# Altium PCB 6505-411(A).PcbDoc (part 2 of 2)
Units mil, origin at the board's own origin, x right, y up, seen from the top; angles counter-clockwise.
Board outline 1549.7 x 1971.6 mil, 4 copper layers (Top Layer, Mid-Layer 1, Mid-Layer 2, Bottom Layer); 80 components, 57 nets, 309 pads, 377 vias.
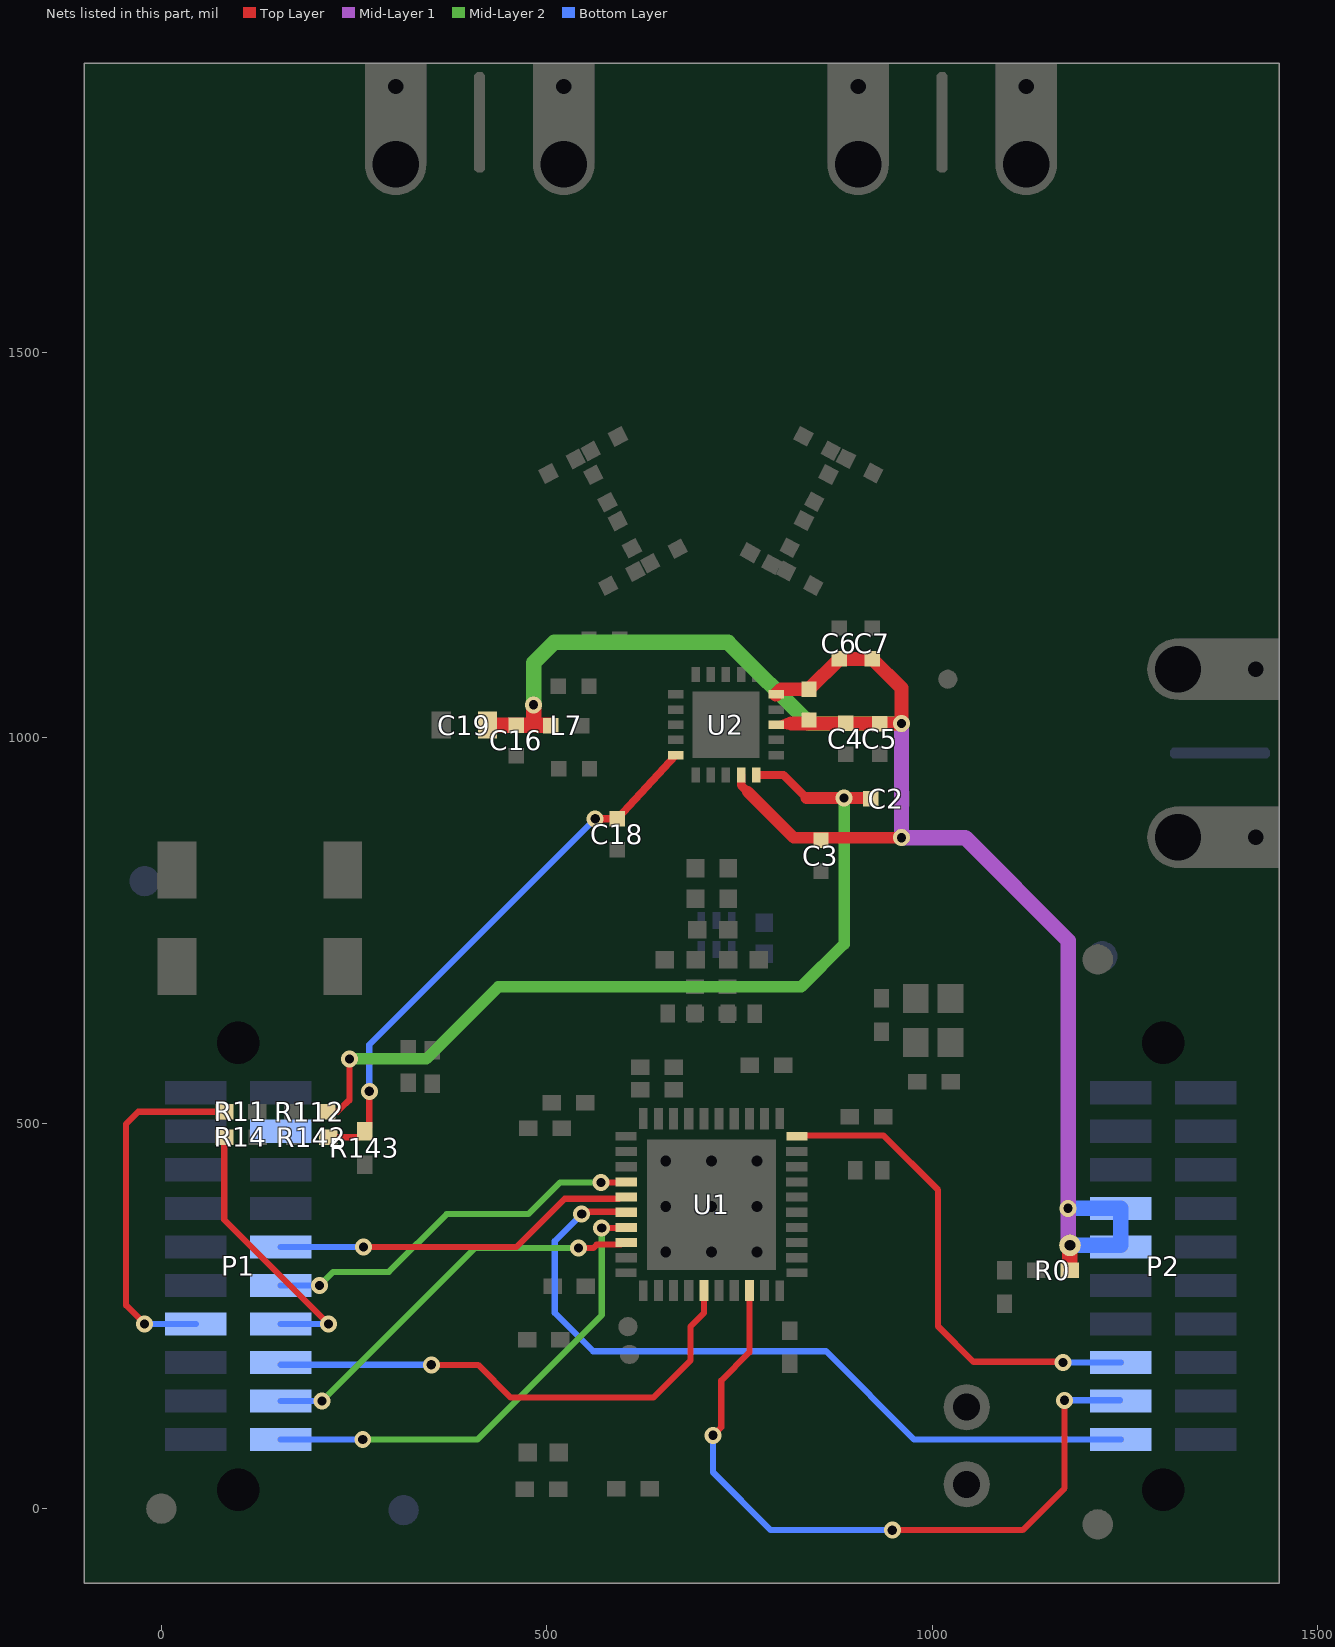
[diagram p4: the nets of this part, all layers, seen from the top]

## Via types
v1: diameter 22, hole 12, Top Layer to Bottom Layer, 281 vias
v2: diameter 22, hole 12, Top Layer to Bottom Layer, tented both sides, 96 vias

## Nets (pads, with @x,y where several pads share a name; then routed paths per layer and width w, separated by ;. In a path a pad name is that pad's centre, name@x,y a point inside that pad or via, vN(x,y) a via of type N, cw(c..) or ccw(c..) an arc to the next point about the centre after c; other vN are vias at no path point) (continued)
P1_1: P1.13 R11.1 | length 469.6
  Top Layer w8: v1(-21.7,239.6) -45.7,263.6 -45.7,499.1 -29.9,514.9 R11.1@81.4,514.9
  Bottom Layer w8: v1(-21.7,239.6) P1.13@44.8,239.6
P1_2: P2.17 U1.8 | length 946.4
  Top Layer w8: v1(715.8,95.1) 726.3,105.6 726.3,166.1 763,202.8 U1.8@763,275.2 ; v1(948.3,-27.9) 1117.3,-27.9 1171.8,26.6 v1(1171.8,140.6) v1@1168.8,140.6
  Bottom Layer w8: v1(715.8,95.1) 715.8,46.9 790.6,-27.9 v1(948.3,-27.9) ; v1(1171.8,140.6) P2.17@1243.8,140.6
P1_3: P1.4
P1_4: P1.14 R14.1 | length 360.3
  Top Layer w8: R14.1@81.6,481.9 81.6,374.8 v1(216.8,239.6)
  Bottom Layer w8: P1.14@154.8,239.6 v1(216.8,239.6)
P1_5: P1.16 U1.5 | length 659.4
  Top Layer w8: v1(350.3,186.6) 410.94,186.49 453.17,144.1 638.3,144.1 686.3,192.1 686.3,236.15 703.9,253.8 U1.5@703.9,275.2
  Bottom Layer w8: P1.16@154.8,186.6 v1(350.3,186.6)
P1_6: P1.18 U1.38 | length 525.5
  Top Layer w8: v1(541.3,338.1) 560.3,338.1 564.7,342.5 U1.38@596.3,342.5
  Mid-Layer 2 w8: v1(208.3,139.6) 406.8,338.1 v1(541.3,338.1)
  Bottom Layer w8: P1.18@154.8,139.6 v1(208.3,139.6)
P1_7: P1.20 U1.37 | length 626.2
  Top Layer w8: v1(571.3,364.2) U1.37@595.3,364.2
  Mid-Layer 2 w8: v1(261.3,89.6) 409.8,89.6 571.3,251.1 v1(571.3,364.2) v1@567.23,360.1
  Bottom Layer w8: P1.20@154.8,89.6 v1(261.3,89.6)
P2_0: P2.19 U1.36 | length 995.8
  Top Layer w8: v1@545.3,385.1 594,385.1 U1.36@595.3,383.8
  Bottom Layer w8: v1(545.3,382.1) 510.3,347.1 510.3,253.93 560.13,204.1 862.3,204.1 976.8,89.6 P2.19@1244.8,89.6
P2_1: P1.10 U1.35 | length 467
  Top Layer w8: v1(262.3,339.6) 460.78,339.6 523.28,402.1 593.9,402.1 U1.35@595.3,403.5
  Bottom Layer w8: P1.10@154.8,339.6 v1(262.3,339.6)
P2_2: P1.12 U1.34 | length 503.6
  Top Layer w8: v1(570.3,423.2) U1.34@603.1,423.2
  Mid-Layer 2 w8: v1(205.3,289.6) 222.8,307.1 295.3,307.1 370.3,382.1 476.3,382.1 517.4,423.2 v1(570.3,423.2)
  Bottom Layer w8: P1.12@154.8,289.6 v1(205.3,289.6)
RESET_N: P2.15 U1.20 | length 648.7
  Top Layer w8: U1.20@821.8,484.3 936.8,484.3 1007.58,413.52 1007.58,236.61 1053.5,190.6 1168.8,190.6 v1(1169.8,189.6)
  Bottom Layer w8: v1(1169.8,189.6) P2.15@1244.8,189.6
RX_EN: C18.2 R142.1 R143.1 U2.20 | length 720.4
  Top Layer w8: R142.1@216.7,481.9 256.5,481.9 259.04,484.42 261.19,486.55 264.08,489.42 269.8,495.1 v1(269.8,541.4)
  Top Layer w10: v1(562.89,894.88) 563.08,895.07 C18.2@591.4,895.07 U2.20@667.31,977.55
  Bottom Layer w8: v1(269.8,541.4) 269.8,601.79 v1(562.89,894.88)
TX_EN: C2.2 R112.1 U2.5 | length 1143.7
  Top Layer w8: R112.1@214.2,514.9 228.3,514.9 228.3,515.1 234,520.9 234.3,520.9 242.8,529.4 244,529.4 v1(244,583.4)
  Top Layer w10: U2.5@771.84,951.76 807.2,951.76 836.99,921.98
  Top Layer w15: 836.99,921.98 v1(885.7,921.98) C2.2@920.3,921.98
  Mid-Layer 2 w15: v1(244,583.4) 343.6,583.4 437.3,677.1 830.3,677.1 885.7,732.5 v1(885.7,921.98)
VDD: C3.2 C4.2 C5.2 C6.2 C7.2 C16.2 C19.2 L7.2 P2.7 P2.9 pad.1@840.2,1063.1 pad.1@1178.8,341.6 pad.2 R0.2 U2.4 U2.8 U2.10 | length 2486.5
  Top Layer w7: 814.38,1023.74 U2.8@797.63,1016.92 ; 817.44,1018.64 U2.8@797.63,1016.92 ; 817.52,1013.09 U2.8@797.63,1016.92
  Top Layer w11: 752.16,938.47 752.16,938.56 ; U2.4@752.16,951.76 752.16,938.56 ; 760.72,930 752.16,938.56 ; C3.2@860.44,871.77 C3.2@861.78,870.42
  Top Layer w15: 760.72,930 820.29,870.42 861.78,870.42 v1(960.3,870.42)
  Top Layer w18: U2.10@797.63,1056.29 804.44,1063.1 pad.1@840.2,1063.1 C6.2@879.6,1102.5 C7.2@922.3,1102.5 960.2,1064.6 v2(960.2,1018.64) 817.44,1018.64
  Top Layer w20: C19.2@423.2,1016.57 C16.2@460.4,1016.57 L7.2@504.71,1016.57 ; 482.89,1017.29 v2(482.89,1042.9) ; R0.2@1178.4,309.6 1178.4,339.6 1178.8,339.6 pad.1@1178.8,341.6
  Mid-Layer 1 w20: v1@960.2,871.02 v2(960.2,1018.64) ; v1(960.3,870.42) 1042.94,870.42 1176.3,737.06 v1(1176.3,389.6) pad.1@1176.3,341.6
  Mid-Layer 2 w11: pad.1@1178.8,339.6 pad.1@1178.8,341.6
  Mid-Layer 2 w20: v2(482.89,1042.9) 482.89,1097.18 509.6,1123.89 735.41,1123.89 840.66,1018.64 v2(960.2,1018.64)
  Bottom Layer w11: pad.1@1178.8,339.6 P2.9@1244.8,339.6
  Bottom Layer w20: v1(1176.3,389.6) P2.7@1244.8,389.6 1244.8,341.6 pad.1@1178.8,341.6
pads on no net: FM1.1 FM2.1 FM3.1 FM4.1 FM5.1 FM6.1 P1.2 P1.8 P1.21 P1.22 P2.1 P2.2 P2.3 P2.4 P2.5 P2.6 P2.8 P2.10 P2.11 P2.12 P2.13 P2.14 P2.16 P2.20 P2.21 P2.22 U2.9 U2.11 U3.2 U3.5 X2.3 X2.4

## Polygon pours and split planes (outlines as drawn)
GND on Top Layer "Top Layer-No Net" (solid, remove dead copper, pour order 1000): -99.7,-96.6 1450,-96.6 1450,1875 -99.7,1875
GND on Mid-Layer 1 "Top Layer-No Net" (solid, pour order 1001): -99.7,1875 -99.7,-96.6 1450,-96.6 1450,1875
GND on Mid-Layer 2 "Top Layer-No Net" (solid, pour order 1002): -99.7,1875 1450,1875 1450,-96.6 -99.7,-96.6
GND on Bottom Layer "Top Layer-No Net" (solid, remove dead copper, pour order 1003): -99.7,-96.6 -99.7,1875 1450,1875 1450,-96.6

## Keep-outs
Keep-Out Layer:
  lines w10: -100,-100 1450,-100 1450,1875 -100,1875 -100,-100

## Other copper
Top Layer:
  pour cut-out: 604.3,409.1 471.3,408.6 472.16,350.98 534.44,288.7 550.8,288.7 581,318.9 604.3,319.1
  pour cut-out: 841.9,324.8 954.6,324.8 956.3,323.1 956.3,246.1 848.3,246.1
  pour cut-out: 32.01,339.93 32.04,339.9 32.04,254.28 32.28,254.28 316.46,-29.9 332.3,-29.9 333.5,25.4 514.9,25.4 515.5,72.9 333.5,72.9 66.3,340.1
  pour cut-out: 900.76,996.98 919.11,996.98 919.11,1007.52 900.76,1007.52
  pour cut-out: 734.3,72.9 734.3,174.1 854.3,174.1 854.3,72.1 835.3,72.1
  pour cut-out: 824.4,289.1 824.4,505.8 599.2,505.8 599.2,289.1
  text "Layer 1" at 4249.29,-2105.02 h75
  text "6505-411" at 3514.19,-2107.72 h75
Mid-Layer 1:
  region net GND: 1317.2,1129.46 1317.2,830.16 1444.2,830.16 1444.2,1129.46
  text "Layer 2" at 4249.29,-2205.02 h75
  text "6505-411" at 3514.19,-2207.72 h75
Mid-Layer 2:
  rectangle net GND: 263.4,1742.2 562.7,1869.2
  rectangle net GND: 863.4,1742.2 1162.7,1869.2
  text "Layer 3" at 4249.29,-2305.02 h75
  text "6505-411" at 3514.19,-2307.72 h75
Bottom Layer:
  pour cut-out: 713.3,210.78 713.3,257.1 815.3,257.1 868.3,303.1 915.3,261.1 855.62,210.78
  text "Layer 4" at 4249.29,-2405.02 h75
  text "6505-411" at 3514.19,-2407.72 h75

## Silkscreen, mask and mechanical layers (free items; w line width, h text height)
Top Overlay:
  lines w5: -44.7,738.6 -44.7,653.6 300.3,653.6 300.3,738.6 ; -44.7,793.6 -44.7,878.6 259.7,878.6 300.3,838.6 300.3,793.6 ; 565.72,254.9 565.8,254.21 565.92,253.52 566.09,252.84 566.3,252.18 566.56,251.53 566.87,250.91 567.22,250.3 567.61,249.72 568.04,249.17 568.51,248.65 569.01,248.17 569.54,247.72 570.11,247.31 570.7,246.94 571.32,246.61 571.95,246.33 572.61,246.09 573.28,245.9 573.96,245.75 574.65,245.65 575.35,245.61 576.05,245.61 576.75,245.65 577.44,245.75 578.12,245.9 578.79,246.09 579.45,246.33 580.08,246.61 580.7,246.94 581.29,247.31 581.86,247.72 582.39,248.17 582.89,248.65 583.36,249.17 583.79,249.72 584.18,250.3 584.53,250.91 584.84,251.53 585.1,252.18 585.31,252.84 585.48,253.52 585.6,254.21 585.68,254.9 585.7,255.6 585.68,256.3 585.6,256.99 585.48,257.68 585.31,258.36 585.1,259.02 584.84,259.67 584.53,260.29 584.18,260.9 583.79,261.48 583.36,262.03 582.89,262.55 582.39,263.03 581.86,263.48 581.29,263.89 580.7,264.26 580.08,264.59 579.45,264.87 578.79,265.11 578.12,265.3 577.44,265.45 576.75,265.55 576.05,265.59 575.35,265.59 574.65,265.55 573.96,265.45 573.28,265.3 572.61,265.11 571.95,264.87 571.32,264.59 570.7,264.26 570.11,263.89 569.54,263.48 569.01,263.03 568.51,262.55 568.04,262.03 567.61,261.48 567.22,260.9 566.87,260.29 566.56,259.67 566.3,259.02 566.09,258.36 565.92,257.68 565.8,256.99 565.72,256.3 565.7,255.6 565.72,254.9 ; 578.7,260.2 578.7,529.1 848.8,529.1 848.8,260.2 578.7,260.2 ; 944.8,-68.4 944.8,231.6 1144.8,231.6 1144.8,-30.9 1094.8,-68.4 944.8,-68.4
  lines w8: 819.8,-50 819.8,-10.4 849,-10.4 853.1,-14.5 853.1,-25 849,-29.1 819.8,-29.1 ; 869.8,-31.2 874,-27 894.8,-27 899,-31.2 899,-45.8 894.8,-50 874,-50 869.8,-45.8 869.8,-14.5 874,-10.4 894.8,-10.4 899,-14.5 ; 260.6,757.8 264.5,749.9 276.3,742 300,742 300,789.3 276.3,789.3 264.5,781.4 260.6,773.5 260.6,757.8
  text "6505-411(A)" at 1397.6,1273.6 h40 r90
  text "RF6505CC2530410(A)" at 152.99,1117.88 h60 r90
  text "Silkscreen Top" at 4249.29,-1905.02 h75
  text "6505-411" at 3514.19,-1907.72 h75
Bottom Overlay:
  lines w5: -65.2,-40.9 -65.2,650.6 259.8,650.6 259.8,-40.9 -65.2,-40.9 ; 673,705.7 673,784.5 759.6,784.5 759.6,705.7 673,705.7 ; 1134.8,-40.9 1134.8,650.6 1459.8,650.6 1459.8,-40.9 1134.8,-40.9
  lines w8: 684.1,773.8 684.4,773.8 684.4,774.2 684.1,774.2 684.1,773.8
  lines w12: -35.5,527.1 -29.3,514.6 -29.3,574 ; 1164.5,527.1 1170.7,514.6 1170.7,574
  text "Silkscreen Bottom" at 4249.29,-2605.02 h75
  text "6505-411" at 3514.19,-2607.72 h75
Top Paste:
  text "Paste Mask Top" at 4249.29,-1805.02 h75
  text "6505-411" at 3514.19,-1807.72 h75
Bottom Paste:
  text "Paste Mask Bottom" at 4249.29,-2705.02 h75
  text "6505-411" at 3514.19,-2707.72 h75
Top Solder:
  text "Soldermask Top" at 4249.29,-2005.02 h75
  text "6505-411" at 3514.19,-2007.72 h75
Bottom Solder:
  text "Soldermask Bottom" at 4249.29,-2505.02 h75
  text "6505-411" at 3514.19,-2507.72 h75
Mechanical 1:
  lines w1: 565.7,255.6 ccw(c575.7,255.6) 585.7,255.6 ; 565.7,255.6 cw(c575.7,255.6) 585.7,255.6 ; 565.7,255.6 ccw(c575.7,255.6) 585.7,255.6 ; 565.7,255.6 cw(c575.7,255.6) 585.7,255.6 ; 565.7,255.6 ccw(c575.7,255.6) 585.7,255.6 ; 565.7,255.6 cw(c575.7,255.6) 585.7,255.6 ; 565.7,255.6 ccw(c575.7,255.6) 585.7,255.6 ; 565.7,255.6 cw(c575.7,255.6) 585.7,255.6
  text "Assembly Top" at 4249.29,-2805.02 h75
  text "6505-411" at 3514.19,-2807.72 h75
Mechanical 2:
  lines w1: -40.87,524.43 cw(c-35.5,527.1) -30.13,529.77 ; -35.3,514.6 ccw(c-29.3,514.6) -23.3,514.6 ; -35.3,574 cw(c-29.3,574) -23.3,574 ; -34.67,511.93 ccw(c-29.3,514.6) -23.93,517.27 ; 1159.13,524.43 cw(c1164.5,527.1) 1169.87,529.77 ; 1164.7,514.6 ccw(c1170.7,514.6) 1176.7,514.6 ; 1164.7,574 cw(c1170.7,574) 1176.7,574 ; 1165.33,511.93 ccw(c1170.7,514.6) 1176.07,517.27
  text "Notes for overall board thickness (for internal use only):" at -6200.71,6994.98 h80
  text "1  Add .0025\" for each outer layer and .0014\" for each inner layer for 1 oz. copper." at -6237.81,6804.09 h80
  text "2  Add .002\" for each outer layer and .0007\" for each inner layer for 0.5 oz. copper." at -6234.81,6590.09 h80
  text "X" at 7594.29,5601.98 h60
  text "X" at 7494.29,5351.98 h60
  text "X" at 7194.29,4851.98 h60
  text "X" at 7894.29,4851.98 h60
  text "X" at 6494.29,4751.98 h60
  text "X" at 8294.29,4751.98 h60
  text "X" at 6744.29,3651.98 h60
  text "X" at 9494.29,3651.98 h60
  text "X" at 7344.29,3401.98 h60
  text "11." at 5246.29,1559.98 h60
  text "ALL 0.156 DIAMETER HOLES ARE +0.002/-0.001 NON-PLATED." at 5446.29,1559.98 h60
  text "12." at 5244.29,1301.98 h60
  text "0.0635 HOLE DIAMETER +/-0.002 TOLERANCE." at 5444.29,1301.98 h60
  text "13." at 5244.29,1051.98 h60
  text "0.0635 HOLE TO TOP METAL REGISTRATION +/-0.001 TOLERANCE." at 5444.29,1051.98 h60
  text "14." at 5244.29,801.98 h60
  text "ALL HOLES ARE TO BE DRILLED WITH THE PRIMARY DRILL, EXCEPT FOR CRITICAL" at 5444.29,801.98 h60
  text "0.0635 HOLES WHICH MAY BE DRILLED WITH OPTICALLY ALIGNED DRILL MACHINE." at 5444.29,701.98 h60
  text "15." at 5244.29,451.98 h60
  text "BOARD FLATNESS SHALL NOT EXCEED 0.005 PER INCH." at 5444.29,451.98 h60
  text "16." at 5244.29,201.98 h60
  text "FIRST ARTICLE INSPECTION OF ALL TOOLING HOLES AND TOP METAL REGISTRATION" at 5444.29,201.98 h60
  text "IS REQUIRED." at 5444.29,101.98 h60
  text "17." at 5244.29,-148.02 h60
  text "100% INSPECTION OF TOP METAL TO REFERENCED 0.0635 TOOLING HOLES IS REQUIRED." at 5444.29,-148.02 h60
  text "18." at 5244.29,-398.02 h60
  text "ALL DIMENSIONAL INSPECTION DATA WILL BE PROVIDED WITH ORDER." at 5444.29,-398.02 h60
  text "* MULTIPLE DRILL PROCESS JOBS SEE .DRL, .DR1, .DR2, etc." at -6298.71,-1790.02 h60
Mechanical 3:
  lines w10: -100,-100 1450,-100 1450,1875 -100,1875 -100,-100
  text "Board Outline" at 4249.29,-2905.02 h75
  text "6505-411" at 3514.19,-2907.72 h75
Mechanical 4:
  drawing of 3692 lines, arcs and shapes, not listed
  text "1" at -5153.65,7231.33 h70
  text "2" at -2328.65,7231.33 h70
  text "3" at 496.35,7231.33 h70
  text "4" at 3321.35,7231.33 h70
  text "5" at 6146.35,7231.33 h70
  text "6" at 8921.35,7231.33 h70
  text "PCB DESIGN" at 4587.41,7007.14 h70
  text "Michael Coolen" at 5602.41,7007.14 h70
  text "PH: 978-670-2246" at 7462.41,7007.14 h70
  text "mcoolen@rfmd.com" at 8847.41,7007.14 h70
  text "CONTACTS" at 3694.35,6918.33 h80
  text "ENGINEERING" at 4590.41,6828.23 h70
  text "Ahmad Abdelmajid" at 5605.41,6828.23 h70
  text "PH: 336-678-7182" at 7465.41,6828.23 h70
  text "AABDELMAJID@rfmd.com" at 8850.41,6828.23 h70
  text "NOTE: SUPPLIER MUST SEND EMAIL TO PCBHOLD@RFMD.COM IN ADDITION TO ABOVE LISTED CONTACTS IF JOB IS PLACED ON HOLD" at 4057.35,6685.33 h55
  text "FABRICATION NOTES: 6505-411(A)421(A).zip" at 5244.29,6351.98 h100
  text "LAYER 1" at -2231.21,6328.48 h50
  text "0.5" at -1766.21,6328.48 h50
  text "OZ BASE COPPER + PLATING" at -1585.21,6328.48 h50
  text ".008" at -6056.21,6190.98 h50
  text "MATL. TYPE" at -5493.71,6190.98 h50
  text "FR-4" at -4543.71,6190.98 h50
  text "Tg 170 DEG C MIN" at -3856.21,6190.98 h50
  text "LAYER 2" at -2231.21,6053.48 h50
  text "1.0" at -1766.21,6053.48 h50
  text "OZ BASE COPPER" at -1585.21,6053.48 h50
  text "1." at 5244.29,6051.98 h60
  text "UNLESS OTHERWISE NOTED, BOARD FABRICATION METHODS MUST COMPLY WITH" at 5445.35,6052.33 h60
  text "A" at -6517.65,5956.33 h70
  text "A" at 10277.35,5956.33 h70
  text "RF MICRO DEVICES PCB FABRICATION SPECIFICATION PCB-21-1001." at 5445.35,5952.33 h60
  text ".012" at -6056.21,5915.98 h50
  text "MATL. TYPE" at -5493.71,5915.98 h50
  text "FR-4" at -4543.71,5915.98 h50
  text "Tg 170 DEG C MIN" at -3856.21,5915.98 h50
  text "A COPY OF PCB-21-1001 CAN BE OBTAINED FROM RF MICRO DEVICES UPON REQUEST." at 5445.35,5852.33 h60
  text "LAYER 3" at -2231.21,5778.48 h50
  text "1.0" at -1766.21,5778.48 h50
  text "OZ BASE COPPER" at -1585.21,5778.48 h50
  text ".008" at -6056.21,5640.98 h50
  text "MATL. TYPE" at -5493.71,5640.98 h50
  text "FR-4" at -4543.71,5640.98 h50
  text "Tg 170 DEG C MIN" at -3856.21,5640.98 h50
  text "0.034 +/- 10%" at -6193.71,5628.48 h50 r90
  text "2." at 5244.29,5601.98 h60
  text "ARTWORK FORMAT:" at 5444.29,5601.98 h60
  text "X" at 6544.29,5601.98 h60
  text "GERBER 274X" at 6694.29,5601.98 h60
  text "ODB++" at 7744.29,5601.98 h60
  text "LAYER 4" at -2231.21,5503.48 h50
  text "0.5" at -1766.21,5503.48 h50
  text "OZ BASE COPPER + PLATING" at -1585.21,5503.48 h50
  text "3." at 5244.29,5351.98 h60
  text "DELIVER BOARDS AS:" at 5444.29,5351.98 h60
  text "X" at 6694.29,5351.98 h60
  text "SINGLES" at 6844.29,5351.98 h60
  text "PANEL/ARRAY, USE FILE PCBPANEL001(X).ZIP" at 7644.29,5351.98 h60
  text "(FOR PANELIZED ORDER PCB FABRICATOR SHALL SEND A COPY OF PANELIZED" at 5544.29,5201.98 h60
  text "GERBER DATA TO CEADS@RFMD.COM)" at 5544.29,5101.98 h60
  text "4." at 5244.29,4851.98 h60
  text "SURFACE FINISH:" at 5444.29,4851.98 h60
  text "X" at 6494.29,4851.98 h60
  text "ENIG" at 6644.29,4851.98 h60
  text "HASL" at 7344.29,4851.98 h60
  text "OSP" at 8044.29,4851.98 h60
  text "ELECTRO-PLATED HARD GOLD" at 6644.29,4751.98 h60
  text "ELECTRO-PLATED SOFT GOLD" at 8394.29,4751.98 h60
  text "5." at 5244.29,4501.98 h60
  text "SOLDERMASK SHALL BE LIQUID PHOTO-IMAGEABLE, GREEN, GLOSSY." at 5444.29,4501.98 h60
  text "6." at 5244.29,4251.98 h60
  text "SILKSCREEN SHALL BE HIGH TEMPERATURE, NON-CONDUCTIVE, WHITE EPOXY BASED INK." at 5444.29,4251.98 h60
  text "7." at 5244.29,4001.98 h60
  text "THE PCB SHALL BE MARKED WITH BOTH THE FABRICATOR'S NAME OR LOGO AND" at 5444.29,4001.98 h60
  text "A DATE CODE SHOWING CALENDAR YEAR AND WEEK (YY/WW)." at 5444.29,3901.98 h60
  text "8." at 5244.29,3651.98 h60
  text "100% ELECTRICAL TEST:" at 5444.29,3651.98 h60
  text "Gerber extracted Netlist" at 6844.29,3651.98 h60
  text "X" at 8294.29,3651.98 h60
  text "IPC-D-356 format" at 8494.29,3651.98 h60
  text "NO E.T." at 9694.29,3651.98 h60
  text "9." at 5244.29,3401.98 h60
  text "CONTROLLED IMPEDANCE:" at 5444.29,3401.98 h60
  text "X" at 6844.29,3401.98 h60
  text "YES" at 6944.29,3401.98 h60
  text "NO" at 7544.29,3401.98 h60
  text "+/-0.001" at 7420.29,3254.98 h60
  text "0.01425" at 7069.29,3251.98 h60
  text "REF LAYER" at 8169.29,3251.98 h60
  text "2" at 8740.29,3251.98 h60
  text "CPW LAYER" at 5944.29,3241.98 h60
  text "1" at 6524.29,3241.98 h60
  text ":" at 6594.29,3241.98 h60
  text "B" at -6517.65,3206.33 h70
  text "B" at 10277.35,3206.33 h70
  text ":" at 6535.29,3153.98 h60
  text "+/-5%" at 7516.29,3056.98 h60
  text "OHMS" at 7247.29,3053.98 h60
  text "TARGET IMPEDANCE:" at 5544.29,3051.98 h60
  text "50" at 7069.29,3051.98 h60
  text "TARGET FREQUENCY:" at 5544.29,2951.98 h60
  text "2.5GHz to 6GHz" at 7069.29,2951.98 h60
  text "DIELECTRIC CONSTANT:" at 5544.29,2851.98 h60
  text "4.26" at 7069.29,2851.98 h60
  text "*" at 5444.29,2676.98 h60
  text "DIELECTRIC(S) THAT CAN BE ADJUSTED TO OBTAIN FINISHED THICKNESS:" at 5544.29,2676.98 h60
  text "LAYER" at 5594.29,2576.98 h60
  text "2-4" at 5913.29,2575.98 h60
  text "*" at 5444.29,2401.98 h60
  text "GERBER DATA SUPPLIED WITH DESIRED FINAL TRACE WIDTHS. PROCESS" at 5544.29,2401.98 h60
  text "COMPENSATION TRACE WIDTH ADJUSTMENT TO BE DONE BY PCB FABRICATOR." at 5544.29,2301.98 h60
  text "LAYER" at 8094.29,2052.98 h60
  text "10." at 5244.29,2051.98 h60
  text "VIA TYPES/ASSOCIATED LAYERS:" at 5444.29,2051.98 h60
  text "THRU-HOLE" at 7244.29,2051.98 h60
  text "1-4" at 8413.29,2051.98 h60
  text "11." at 5263.1,1908.8 h60
  text "METAL TO NEAR EDGE AT 3 LOCATIONS IS NECESSARY.  THE PRODUCT PERFORMANCE" at 5463.1,1908.8 h60
  text "IS SIGNIFICANTLY COMPROMISED WITH LARGE PULL BACKS." at 5469.1,1806.8 h60
  text "C" at -6517.65,456.33 h70
  text "C" at 10277.35,456.33 h70
  text "FAMILY P/N:" at 7306.29,-1984.02 h45
  text "6505" at 7343.69,-2175.12 h120
  text "D" at -6517.65,-2293.67 h70
  text "D" at 10277.35,-2293.67 h70
  text "TITLE:" at 7306.29,-2334.02 h45
  text "RF6505CC2530-410 Evaluation PCB" at 7343.69,-2475.12 h120
  text "7628 Thorndike Road" at 5806.29,-2479.02 h80
  text "PCB PART NO:" at 7306.29,-2609.02 h45
  text "Greensboro, NC 27409" at 5786.29,-2629.02 h80
  text "Phone: 336-664-1233" at 5776.29,-2779.02 h80
  text "6505-411" at 7343.69,-2778.77 h120
  text "DOC NO:" at 7306.29,-2929.02 h45
  text "REV:" at 9806.29,-2929.02 h45
  text "DATE:" at 5757.35,-2933.67 h45
  text "07/26/11" at 6036.29,-3034.02 h100
  text "6505-421" at 7353.69,-3105.12 h120
  text "SIZE:" at 7306.29,-3229.38 h45
  text "SCALE:" at 7742.72,-3229.38 h45
  text "PAGE:" at 8868.79,-3229.38 h45
  text "ALL DIMENSIONS IN INCHES" at 5971.29,-3254.02 h50
  text "A" at 9896.29,-3259.02 h250
  text "1 OF" at 9156.29,-3334.02 h100
  text "1" at 9556.29,-3334.02 h100
  text "B" at 7483.79,-3346.52 h120
  text "DO NOT SCALE" at 7893.79,-3359.02 h80
  text "UNLESS OTHERWISE SPECIFIED" at 5926.29,-3364.02 h50
  text "1" at -5153.65,-3568.67 h70
  text "2" at -2328.65,-3568.67 h70
  text "3" at 496.35,-3568.67 h70
  text "4" at 3321.35,-3568.67 h70
  text "5" at 6146.35,-3568.67 h70
  text "6" at 8921.35,-3568.67 h70
  text "ENG/PT PCB ASY DWG REV.1" at -6543.71,-3584.02 h30
Mechanical 15:
  drawing of 3472 lines, arcs and shapes, not listed
  text "1" at -5153.71,7230.98 h70
  text "2" at -2328.71,7230.98 h70
  text "3" at 496.29,7230.98 h70
  text "4" at 3321.29,7230.98 h70
  text "5" at 6146.29,7230.98 h70
  text "6" at 8921.29,7230.98 h70
  text "PCB DESIGN" at 4587.35,7006.78 h70
  text "Michael Coolen" at 5602.35,7006.78 h70
  text "PH: 978-670-2246" at 7462.35,7006.78 h70
  text "mcoolen@rfmd.com" at 8847.35,7006.78 h70
  text "NOTES :" at -6252.81,6999.09 h80
  text "CONTACTS" at 3694.29,6917.98 h80
  text "ENGINEERING" at 4590.35,6827.88 h70
  text "Ahmad Abdelmajid" at 5605.35,6827.88 h70
  text "PH: 336-678-7182" at 7465.35,6827.88 h70
  text "AABDELMAJID@rfmd.com" at 8850.35,6827.88 h70
  text "1  WORKMANSHIP & SOLDER PER IPC-A-610C, CLASS 2." at -6237.81,6804.09 h80
  text "2  FOR FURTHER INSTRUCTION ON ASSEMBLY CHECK NOTES ON BILL OF MATERIAL." at -6234.81,6590.09 h80
  text "A" at -6517.71,5955.98 h70
  text "A" at 10277.29,5955.98 h70
  text "B" at -6517.71,3205.98 h70
  text "B" at 10277.29,3205.98 h70
  text "C" at -6517.71,455.98 h70
  text "C" at 10277.29,455.98 h70
  text "FAMILY P/N:" at 7306.22,-1984.38 h45
  text "6505" at 7343.62,-2175.48 h120
  text "D" at -6517.71,-2294.02 h70
  text "D" at 10277.29,-2294.02 h70
  text "TITLE:" at 7306.22,-2334.38 h45
  text "RF6505CC2530-410 Evaluation PCB" at 7343.62,-2475.48 h120
  text "7628 Thor" at 5806.22,-2479.38 h80
  text "ndi" at 6396.22,-2479.38 h80
  text "ke Road" at 6566.22,-2479.38 h80
  text "PCB PART NO:" at 7306.22,-2609.38 h45
  text "Greensboro, NC 27409" at 5786.22,-2629.38 h80
  text "Phone: 336-664-1233" at 5776.22,-2779.38 h80
  text "6505-411" at 7343.62,-2779.12 h120
  text "DOC NO:" at 7306.22,-2929.38 h45
  text "REV:" at 9806.22,-2929.38 h45
  text "DATE:" at 5757.29,-2934.02 h45
  text "07/26/11" at 6036.22,-3034.38 h100
  text "6505-471" at 7332.69,-3103.12 h120
  text "SIZE:" at 7306.22,-3229.73 h45
  text "SCALE:" at 7742.66,-3229.73 h45
  text "PAGE:" at 8868.72,-3229.73 h45
  text "ALL DIMENSIONS IN INCHES" at 5971.22,-3254.38 h50
  text "A" at 9896.22,-3259.38 h250
  text "1 OF" at 9156.22,-3334.38 h100
  text "1" at 9556.22,-3334.38 h100
  text "B" at 7483.72,-3346.88 h120
  text "DO NOT SCALE" at 7893.72,-3359.38 h80
  text "UNLESS OTHERWISE SPECIFIED" at 5926.22,-3364.38 h50
  text "1" at -5153.71,-3569.02 h70
  text "2" at -2328.71,-3569.02 h70
  text "3" at 496.29,-3569.02 h70
  text "4" at 3321.29,-3569.02 h70
  text "5" at 6146.29,-3569.02 h70
  text "6" at 8921.29,-3569.02 h70
  text "ENG/PT PCB FAB DWG REV.1" at -6543.78,-3584.38 h30
Mechanical 16:
  drawing of 3465 lines, arcs and shapes, not listed
  text "6" at -5109.71,7231.98 h70
  text "5" at -2284.71,7231.98 h70
  text "4" at 540.29,7231.98 h70
  text "3" at 3365.29,7231.98 h70
  text "2" at 6190.29,7231.98 h70
  text "1" at 8965.29,7231.98 h70
  text "A" at -6463.71,5956.98 h70
  text "A" at 10331.29,5956.98 h70
  text "B" at -6463.71,3206.98 h70
  text "B" at 10331.29,3206.98 h70
  text "C" at -6463.71,456.98 h70
  text "C" at 10331.29,456.98 h70
  text "FAMILY P/N:" at -3492.65,-1983.38 h45
  text "RFSM6505CC2530" at -3889.4,-2170 h120
  text "D" at -6463.71,-2293.02 h70
  text "D" at 10331.29,-2293.02 h70
  text "TITLE:" at -3492.65,-2333.38 h45
  text "ke Road" at -2752.65,-2478.38 h80
  text "ndi" at -2582.65,-2478.38 h80
  text "7628 Thor" at -1992.65,-2478.38 h80
  text "RFSM6505CC2530 Evaluation PCB" at -3499,-2483.9 h120
  text "PCB PART NO:" at -3492.65,-2608.38 h45
  text "Greensboro, NC 27409" at -1972.65,-2628.38 h80
  text "Phone: 336-664-1233" at -1962.65,-2778.38 h80
  text "RFSM6505CC2530410" at -3870.8,-2800.5 h120
  text "REV:" at -5992.65,-2928.38 h45
  text "DOC NO:" at -3492.65,-2928.38 h45
  text "DATE:" at -1943.71,-2933.02 h45
  text "07/26/11" at -2222.65,-3033.38 h100
  text "RFSM6505CC2530470" at -3894,-3083.3 h120
  text "PAGE:" at -5055.15,-3228.73 h45
  text "SCALE:" at -3929.09,-3228.73 h45
  text "SIZE:" at -3492.65,-3228.73 h45
  text "ALL DIMENSIONS IN INCHES" at -2157.65,-3253.38 h50
  text "A" at -6082.65,-3258.38 h250
  text "2" at -5742.65,-3333.38 h100
  text "2 OF" at -5342.65,-3333.38 h100
  text "B" at -3670.15,-3345.88 h120
  text "DO NOT SCALE" at -4080.15,-3358.38 h80
  text "UNLESS OTHERWISE SPECIFIED" at -2112.65,-3363.38 h50
  text "6" at -5109.71,-3568.02 h70
  text "5" at -2284.71,-3568.02 h70
  text "4" at 540.29,-3568.02 h70
  text "3" at 3365.29,-3568.02 h70
  text "2" at 6190.29,-3568.02 h70
  text "1" at 8965.29,-3568.02 h70
Drill Drawing:
  text ".Legend" at -6160.71,-1584.02 h75
  text "Dimension/Drill" at 4249.29,-3005.02 h75
  text "6505-411" at 3514.19,-3007.72 h75

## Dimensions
0,0 to -100,-100 on Drill Drawing
0,0 to -100,-100 on Drill Drawing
